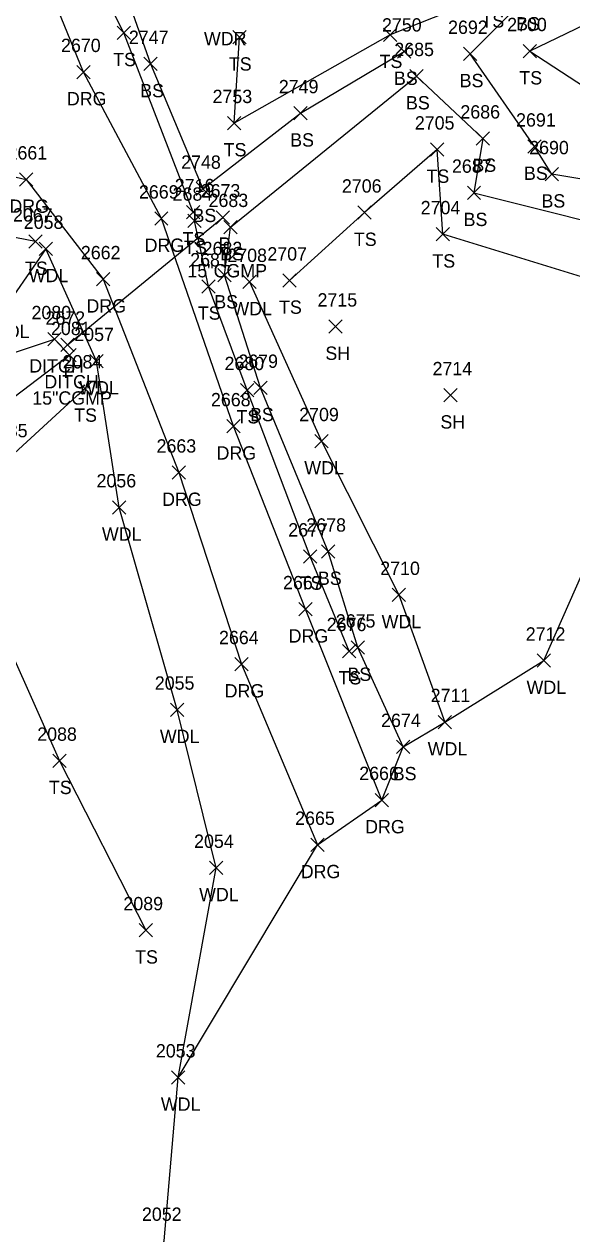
# Model space of a CAD drawing. Extents: x 1633660 to 1636532, y 388643 to 392631.
# Drawn here: x 1634828.3 to 1634910.5, y 389113.6 to 389295.1 of the extents above; entities that cross this region are included whole.
import ezdxf

# ---------------------------------------------------------------- set-up
doc = ezdxf.new("R2010")
doc.units = 0
for name, color, linetype in [('D_A', 7, 'Continuous'), ('D_C', 7, 'Continuous'), ('D_I', 7, 'Continuous'), ('D_TIC', 7, 'Continuous'), ('DCP', 7, 'Continuous'), ('DD', 7, 'Continuous'), ('L_A', 7, 'Continuous'), ('L_I', 7, 'Continuous'), ('L_TIC', 7, 'Continuous'), ('LAWA', 7, 'Continuous'), ('LELB', 7, 'Continuous'), ('LSOGP', 7, 'Continuous'), ('R_A', 7, 'Continuous'), ('R_I', 7, 'Continuous'), ('R_TIC', 7, 'Continuous'), ('RDG', 7, 'Continuous')]:
    doc.layers.add(name, color=color, linetype=linetype)

msp = doc.modelspace()

# ---------------------------------------------------------------- linework, layer by layer
at = {"layer": 'D_TIC'}
for points in [[(1634857.12, 389265.13), (1634859.12, 389267.13)], [(1634859.12, 389265.13), (1634857.12, 389267.13)], [(1634831.84, 389246.85), (1634833.84, 389248.85)], [(1634833.84, 389246.85), (1634831.84, 389248.85)], [(1634833.82, 389246.03), (1634835.82, 389248.03)], [(1634835.82, 389246.03), (1634833.82, 389248.03)], [(1634834.1, 389244.47), (1634836.1, 389246.47)], [(1634836.1, 389244.47), (1634834.1, 389246.47)]]:
    msp.add_lwpolyline(points, dxfattribs=at)
at = {"layer": 'DCP'}
msp.add_lwpolyline([(1634834.82, 389247.03), (1634858.12, 389266.13)], dxfattribs=at)
at = {"layer": 'DD'}
msp.add_lwpolyline([(1634800.59, 389227.46), (1634807.22, 389234.42), (1634816.37, 389242.36), (1634832.84, 389247.85), (1634835.1, 389245.47), (1634819.6, 389233.69), (1634805.01, 389224.04)], dxfattribs=at)
at = {"layer": 'L_TIC'}
for points in [[(1634842.26, 389292.83), (1634844.26, 389294.83)], [(1634844.26, 389292.83), (1634842.26, 389294.83)], [(1634859.63, 389292.16), (1634861.63, 389294.16)], [(1634861.63, 389292.16), (1634859.63, 389294.16)], [(1634882.26, 389292.55), (1634884.26, 389294.55)], [(1634884.26, 389292.55), (1634882.26, 389294.55)], [(1634884.38, 389290.02), (1634886.38, 389292.02)], [(1634886.38, 389290.02), (1634884.38, 389292.02)], [(1634894.25, 389289.67), (1634896.25, 389291.67)], [(1634896.25, 389289.67), (1634894.25, 389291.67)], [(1634903.24, 389290.08), (1634905.24, 389292.08)], [(1634905.24, 389290.08), (1634903.24, 389292.08)], [(1634846.29, 389288.16), (1634848.29, 389290.16)], [(1634848.29, 389288.16), (1634846.29, 389290.16)], [(1634886.19, 389286.34), (1634888.19, 389288.34)], [(1634888.19, 389286.34), (1634886.19, 389288.34)], [(1634868.81, 389280.76), (1634870.81, 389282.76)], [(1634870.81, 389280.76), (1634868.81, 389282.76)], [(1634858.85, 389279.29), (1634860.85, 389281.29)], [(1634860.85, 389279.29), (1634858.85, 389281.29)], [(1634896.16, 389276.97), (1634898.16, 389278.97)], [(1634898.16, 389276.97), (1634896.16, 389278.97)], [(1634889.3, 389275.32), (1634891.3, 389277.32)], [(1634891.3, 389275.32), (1634889.3, 389277.32)], [(1634903.9, 389275.76), (1634905.9, 389277.76)], [(1634905.9, 389275.76), (1634903.9, 389277.76)], [(1634906.52, 389271.61), (1634908.52, 389273.61)], [(1634908.52, 389271.61), (1634906.52, 389273.61)], [(1634854.14, 389269.43), (1634856.14, 389271.43)], [(1634856.14, 389269.43), (1634854.14, 389271.43)], [(1634894.84, 389268.83), (1634896.84, 389270.83)], [(1634896.84, 389268.83), (1634894.84, 389270.83)], [(1634852.67, 389265.92), (1634854.67, 389267.92)], [(1634854.67, 389265.92), (1634852.67, 389267.92)], [(1634878.4, 389265.85), (1634880.4, 389267.85)], [(1634880.4, 389265.85), (1634878.4, 389267.85)], [(1634852.9, 389264.64), (1634854.9, 389266.64)], [(1634854.9, 389264.64), (1634852.9, 389266.64)], [(1634858.3, 389263.69), (1634860.3, 389265.69)], [(1634860.3, 389263.69), (1634858.3, 389265.69)], [(1634890.18, 389262.6), (1634892.18, 389264.6)], [(1634892.18, 389262.6), (1634890.18, 389264.6)], [(1634829.02, 389261.5), (1634831.02, 389263.5)], [(1634831.02, 389261.5), (1634829.02, 389263.5)], [(1634830.58, 389260.41), (1634832.58, 389262.41)], [(1634832.58, 389260.41), (1634830.58, 389262.41)], [(1634857.4, 389256.47), (1634859.4, 389258.47)], [(1634859.4, 389256.47), (1634857.4, 389258.47)], [(1634854.97, 389254.78), (1634856.97, 389256.78)], [(1634856.97, 389254.78), (1634854.97, 389256.78)], [(1634861.15, 389255.44), (1634863.15, 389257.44)], [(1634863.15, 389255.44), (1634861.15, 389257.44)], [(1634867.16, 389255.66), (1634869.16, 389257.66)], [(1634869.16, 389255.66), (1634867.16, 389257.66)], [(1634874.05, 389248.75), (1634876.05, 389250.75)], [(1634876.05, 389248.75), (1634874.05, 389250.75)], [(1634838.17, 389243.57), (1634840.17, 389245.57)], [(1634840.17, 389243.57), (1634838.17, 389245.57)], [(1634836.41, 389239.46), (1634838.41, 389241.46)], [(1634838.41, 389239.46), (1634836.41, 389241.46)], [(1634860.78, 389239.21), (1634862.78, 389241.21)], [(1634862.78, 389239.21), (1634860.78, 389241.21)], [(1634862.77, 389239.55), (1634864.77, 389241.55)], [(1634864.77, 389239.55), (1634862.77, 389241.55)], [(1634891.32, 389238.44), (1634893.32, 389240.44)], [(1634893.32, 389238.44), (1634891.32, 389240.44)], [(1634871.94, 389231.55), (1634873.94, 389233.55)], [(1634873.94, 389231.55), (1634871.94, 389233.55)], [(1634841.56, 389221.61), (1634843.56, 389223.61)], [(1634843.56, 389221.61), (1634841.56, 389223.61)], [(1634872.97, 389214.97), (1634874.97, 389216.97)], [(1634874.97, 389214.97), (1634872.97, 389216.97)], [(1634870.25, 389214.24), (1634872.25, 389216.24)], [(1634872.25, 389214.24), (1634870.25, 389216.24)], [(1634883.55, 389208.47), (1634885.55, 389210.47)], [(1634885.55, 389208.47), (1634883.55, 389210.47)], [(1634877.4, 389200.57), (1634879.4, 389202.57)], [(1634879.4, 389200.57), (1634877.4, 389202.57)], [(1634876.09, 389200.04), (1634878.09, 389202.04)], [(1634878.09, 389200.04), (1634876.09, 389202.04)], [(1634905.31, 389198.61), (1634907.31, 389200.61)], [(1634907.31, 389198.61), (1634905.31, 389200.61)], [(1634850.26, 389191.25), (1634852.26, 389193.25)], [(1634852.26, 389191.25), (1634850.26, 389193.25)], [(1634890.47, 389189.38), (1634892.47, 389191.38)], [(1634892.47, 389189.38), (1634890.47, 389191.38)], [(1634884.2, 389185.65), (1634886.2, 389187.65)], [(1634886.2, 389185.65), (1634884.2, 389187.65)], [(1634832.61, 389183.58), (1634834.61, 389185.58)], [(1634834.61, 389183.58), (1634832.61, 389185.58)], [(1634856.15, 389167.51), (1634858.15, 389169.51)], [(1634858.15, 389167.51), (1634856.15, 389169.51)], [(1634845.56, 389158.14), (1634847.56, 389160.14)], [(1634847.56, 389158.14), (1634845.56, 389160.14)], [(1634850.42, 389136.05), (1634852.42, 389138.05)], [(1634852.42, 389136.05), (1634850.42, 389138.05)]]:
    msp.add_lwpolyline(points, dxfattribs=at)
at = {"layer": 'LAWA'}
for points in [[(1634811.65, 389038.97), (1634818.43, 389066.63), (1634837.85, 389085.95), (1634849.33, 389112.53), (1634851.42, 389137.05), (1634857.15, 389168.51), (1634851.26, 389192.25), (1634842.56, 389222.61), (1634839.17, 389244.57), (1634831.58, 389261.41), (1634825.76, 389253.02), (1634813.48, 389243.97), (1634799.9, 389233.03), (1634793.09, 389231.99)], [(1634862.15, 389256.44), (1634872.94, 389232.55), (1634884.55, 389209.47), (1634891.47, 389190.38), (1634906.31, 389199.61)]]:
    msp.add_lwpolyline(points, dxfattribs=at)
at = {"layer": 'LELB'}
for points in [[(1634853.67, 389266.92), (1634843.26, 389293.83), (1634835.93, 389308.48), (1634845.9, 389329.19), (1634866.35, 389364.08), (1634881.84, 389393.3), (1634902.23, 389427.8), (1634921.56, 389460.56), (1634945.17, 389499.39)], [(1634836.88, 389309.12), (1634847.11, 389328.98), (1634867.58, 389363.57), (1634883.07, 389392.29), (1634903.19, 389426.99), (1634922.04, 389459.89), (1634948, 389498.04), (1634923.75, 389458.93), (1634905.81, 389425.35), (1634884.7, 389391.31), (1634871.53, 389358.51), (1634859.27, 389332.46), (1634847.91, 389314.24), (1634841.4, 389305.77), (1634847.29, 389289.16), (1634855.14, 389270.43), (1634869.81, 389281.76), (1634885.38, 389291.02)], [(1634928.63, 389269.14), (1634907.52, 389272.61), (1634904.9, 389276.76), (1634895.25, 389290.67), (1634903.72, 389299.19), (1634934.18, 389317.7), (1634977.92, 389336.59)], [(1634973.77, 389327.89), (1634946.43, 389316.57), (1634927.4, 389302.27), (1634904.24, 389291.08), (1634923.1, 389278.79), (1634935.69, 389273.59)], [(1634898.55, 389299.63), (1634883.26, 389293.55), (1634859.85, 389280.29), (1634860.63, 389293.16)], [(1634885.2, 389186.65), (1634878.4, 389201.57), (1634873.97, 389215.97), (1634863.77, 389240.55), (1634858.4, 389257.47), (1634859.3, 389264.69), (1634887.19, 389287.34), (1634897.16, 389277.97), (1634895.84, 389269.83), (1634924.39, 389262.66)], [(1634921.74, 389254.21), (1634891.18, 389263.6), (1634890.3, 389276.32), (1634879.4, 389266.85), (1634868.16, 389256.66)], [(1634830.02, 389262.5), (1634817.02, 389265.02), (1634802.1, 389255.3), (1634782.18, 389232.92)], [(1634877.09, 389201.04), (1634871.25, 389215.24), (1634861.78, 389240.21), (1634855.97, 389255.78), (1634853.9, 389265.64)], [(1634837.41, 389240.46), (1634826.21, 389230.13), (1634810.52, 389219.4), (1634822.42, 389209.64), (1634833.61, 389184.58), (1634846.56, 389159.14)]]:
    msp.add_lwpolyline(points, dxfattribs=at)
at = {"layer": 'LSOGP'}
msp.add_lwpolyline([(1634849.33, 389112.53), (1634851.42, 389137.05), (1634872.35, 389171.96), (1634882.02, 389178.69), (1634885.2, 389186.65), (1634891.47, 389190.38), (1634906.31, 389199.61), (1634914.86, 389218.99), (1634921.74, 389254.21), (1634924.39, 389262.66), (1634928.63, 389269.14), (1634935.69, 389273.59), (1634973.77, 389327.89), (1634977.92, 389336.59), (1634977.33, 389342.4), (1635007.58, 389384.86), (1635032.21, 389403.07), (1635035.11, 389418.19)], dxfattribs=at)
at = {"layer": 'R_TIC'}
for points in [[(1634836.23, 389286.95), (1634838.23, 389288.95)], [(1634838.23, 389286.95), (1634836.23, 389288.95)], [(1634827.6, 389270.82), (1634829.6, 389272.82)], [(1634829.6, 389270.82), (1634827.6, 389272.82)], [(1634847.9, 389264.96), (1634849.9, 389266.96)], [(1634849.9, 389264.96), (1634847.9, 389266.96)], [(1634839.18, 389255.85), (1634841.18, 389257.85)], [(1634841.18, 389255.85), (1634839.18, 389257.85)], [(1634858.71, 389233.78), (1634860.71, 389235.78)], [(1634860.71, 389233.78), (1634858.71, 389235.78)], [(1634850.53, 389226.83), (1634852.53, 389228.83)], [(1634852.53, 389226.83), (1634850.53, 389228.83)], [(1634869.53, 389206.32), (1634871.53, 389208.32)], [(1634871.53, 389206.32), (1634869.53, 389208.32)], [(1634859.92, 389198.08), (1634861.92, 389200.08)], [(1634861.92, 389198.08), (1634859.92, 389200.08)], [(1634881.02, 389177.69), (1634883.02, 389179.69)], [(1634883.02, 389177.69), (1634881.02, 389179.69)], [(1634871.35, 389170.96), (1634873.35, 389172.96)], [(1634873.35, 389170.96), (1634871.35, 389172.96)]]:
    msp.add_lwpolyline(points, dxfattribs=at)
at = {"layer": 'RDG'}
for points in [[(1634882.02, 389178.69), (1634870.53, 389207.32), (1634859.71, 389234.78), (1634848.9, 389265.96), (1634837.23, 389287.95), (1634831.04, 389303.03)], [(1634812.72, 389275.52), (1634828.6, 389271.82), (1634840.18, 389256.85), (1634851.53, 389227.83), (1634860.92, 389199.08), (1634872.35, 389171.96)]]:
    msp.add_lwpolyline(points, dxfattribs=at)

# ---------------------------------------------------------------- texts
at = {"layer": 'D_A'}
for s, p in [('P', (1634857.5, 389261.13)), ('DITCH', (1634829.07, 389242.85)), ('P', (1634834.2, 389242.03)), ('DITCH', (1634831.34, 389240.47))]:
    msp.add_text(s, height=2, dxfattribs=at).set_placement(p)
at = {"layer": 'D_C'}
for p in [(1634852.82, 389257.13), (1634829.52, 389238.03)]:
    msp.add_text('15"CGMP', height=2, dxfattribs=at).set_placement(p)
at = {"layer": 'D_I'}
for s, p in [('2673', (1634854.81, 389269.13)), ('2080', (1634829.41, 389250.85)), ('2672', (1634831.51, 389250.03)), ('2081', (1634832.33, 389248.47))]:
    msp.add_text(s, height=2, dxfattribs=at).set_placement(p)
at = {"layer": 'L_A'}
for s, p in [('TS', (1634896.96, 389294.63)), ('BS', (1634902.16, 389294.19)), ('WDR', (1634855.3, 389291.96)), ('TS', (1634841.67, 389288.83)), ('TS', (1634859.04, 389288.16)), ('TS', (1634881.67, 389288.55)), ('BS', (1634883.82, 389286.02)), ('BS', (1634893.69, 389285.67)), ('TS', (1634902.65, 389286.08)), ('BS', (1634845.73, 389284.16)), ('BS', (1634885.63, 389282.34)), ('BS', (1634868.25, 389276.76)), ('TS', (1634858.26, 389275.29)), ('BS', (1634895.6, 389272.97)), ('TS', (1634888.71, 389271.32)), ('BS', (1634903.34, 389271.76)), ('BS', (1634905.97, 389267.61)), ('BS', (1634853.58, 389265.43)), ('BS', (1634894.28, 389264.83)), ('TS', (1634852.08, 389261.92)), ('TS', (1634877.81, 389261.85)), ('TS', (1634852.31, 389260.64)), ('BS', (1634857.74, 389259.69)), ('TS', (1634889.59, 389258.6)), ('TS', (1634828.43, 389257.5)), ('WDL', (1634829, 389256.41)), ('BS', (1634856.85, 389252.47)), ('WDL', (1634859.57, 389251.44)), ('TS', (1634866.57, 389251.66)), ('TS', (1634854.38, 389250.78)), ('WDL', (1634823.18, 389248.02)), ('SH', (1634873.53, 389244.75)), ('WDL', (1634836.59, 389239.57)), ('TS', (1634835.82, 389235.46)), ('TS', (1634860.19, 389235.21)), ('BS', (1634862.22, 389235.55)), ('SH', (1634890.8, 389234.44)), ('WDL', (1634870.36, 389227.55)), ('WDL', (1634839.98, 389217.61)), ('TS', (1634869.66, 389210.24)), ('BS', (1634872.41, 389210.97)), ('WDL', (1634881.97, 389204.47)), ('BS', (1634876.84, 389196.57)), ('TS', (1634875.5, 389196.04)), ('WDL', (1634903.73, 389194.61)), ('WDL', (1634848.68, 389187.25)), ('WDL', (1634888.89, 389185.38)), ('BS', (1634883.64, 389181.65)), ('TS', (1634832.02, 389179.58)), ('WDL', (1634854.57, 389163.51)), ('TS', (1634844.97, 389154.14)), ('WDL', (1634848.83, 389132.05))]:
    msp.add_text(s, height=2, dxfattribs=at).set_placement(p)
at = {"layer": 'L_I'}
for s, p in [('2750', (1634882.03, 389294.02)), ('2692', (1634891.95, 389293.67)), ('2700', (1634900.82, 389294.08)), ('2747', (1634844.03, 389292.16)), ('2685', (1634883.88, 389290.34)), ('2749', (1634866.54, 389284.76)), ('2753', (1634856.59, 389283.29)), ('2686', (1634893.8, 389280.97)), ('2705', (1634886.96, 389279.32)), ('2691', (1634902.16, 389279.76)), ('2690', (1634904.13, 389275.61)), ('2748', (1634851.88, 389273.43)), ('2687', (1634892.53, 389272.83)), ('2716', (1634850.92, 389269.92)), ('2706', (1634876.01, 389269.85)), ('2684', (1634850.59, 389268.64)), ('2683', (1634855.99, 389267.69)), ('2067', (1634826.63, 389265.5)), ('2704', (1634887.84, 389266.6)), ('2058', (1634828.25, 389264.41)), ('2682', (1634855.1, 389260.47)), ('2681', (1634853.23, 389258.78)), ('2708', (1634858.81, 389259.44)), ('2707', (1634864.82, 389259.66)), ('2715', (1634872.35, 389252.75)), ('2057', (1634835.83, 389247.57)), ('2084', (1634834.08, 389243.46)), ('2680', (1634858.39, 389243.21)), ('2679', (1634860.46, 389243.55)), ('2714', (1634889.62, 389242.44)), ('2709', (1634869.6, 389235.55)), ('2085', (1634822.87, 389233.13)), ('2056', (1634839.17, 389225.61)), ('2678', (1634870.67, 389218.97)), ('2677', (1634867.95, 389218.24)), ('2710', (1634881.77, 389212.47)), ('2676', (1634873.73, 389204.04)), ('2675', (1634875.09, 389204.57)), ('2712', (1634903.61, 389202.61)), ('2055', (1634847.92, 389195.25)), ('2711', (1634889.34, 389193.38)), ('2674', (1634881.89, 389189.65)), ('2088', (1634830.27, 389187.58)), ('2054', (1634853.82, 389171.51)), ('2089', (1634843.21, 389162.14)), ('2053', (1634848.08, 389140.05)), ('2052', (1634845.99, 389115.53))]:
    msp.add_text(s, height=2, dxfattribs=at).set_placement(p)
at = {"layer": 'R_A'}
for p in [(1634834.72, 389282.95), (1634826.09, 389266.82), (1634846.39, 389260.96), (1634837.66, 389251.85), (1634857.19, 389229.78), (1634849.02, 389222.83), (1634868.01, 389202.32), (1634858.4, 389194.08), (1634879.5, 389173.69), (1634869.83, 389166.96)]:
    msp.add_text('DRG', height=2, dxfattribs=at).set_placement(p)
at = {"layer": 'R_I'}
for s, p in [('2670', (1634833.84, 389290.95)), ('2661', (1634825.81, 389274.82)), ('2669', (1634845.54, 389268.96)), ('2662', (1634836.82, 389259.85)), ('2668', (1634856.35, 389237.78)), ('2663', (1634848.18, 389230.83)), ('2667', (1634867.17, 389210.32)), ('2664', (1634857.56, 389202.08)), ('2666', (1634878.61, 389181.69)), ('2665', (1634868.99, 389174.96))]:
    msp.add_text(s, height=2, dxfattribs=at).set_placement(p)

doc.saveas('drawing.dxf')
